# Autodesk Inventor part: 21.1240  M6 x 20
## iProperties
Created: 2006-02
Part Number: 21.1240  M6 x 20
Material: Steel, Mild
Description: Cylinder Head Cap Screw
Document SubType Name: Modeling
Standard: DIN 7984
Designer: Andy Moles
Standards Organization: DIN
Language: en-US
Size Designation: M6 x 20
Categories: <MemberInstance><Categories><Category DisplayName="Fasteners" InternalName="e4da775c-781d-43d5-af7c-5136215cf5a6" Mnemonic="FSTN"><Category DisplayName="Bolts"
Density: 7.86 g/cm^3
Author: Andy Moles
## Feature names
1. Body [Revolution]
2. Slot [Extrusion]
3. Fillet1
4. Chamfer1
